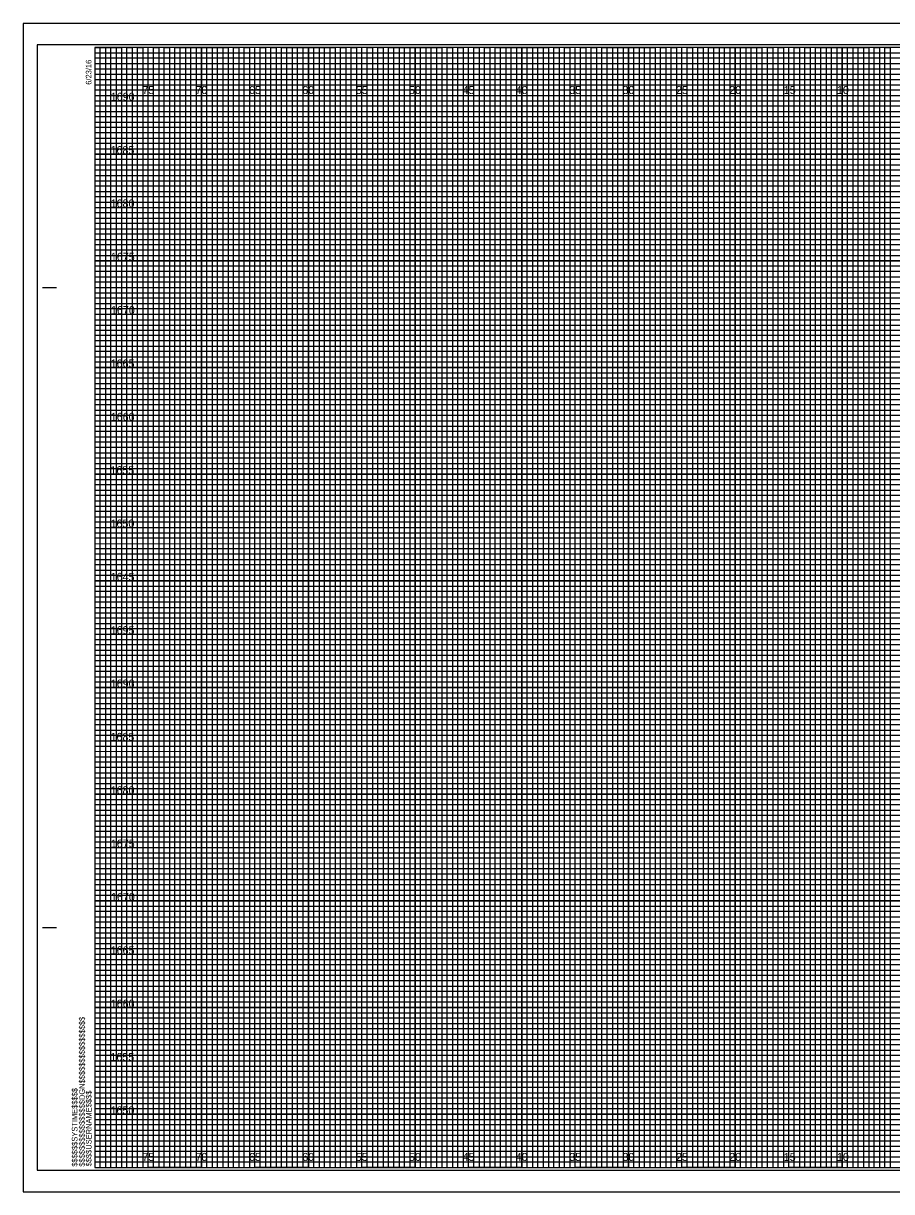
# Model space of a CAD drawing. Extents: x 224 to 392, y 1 to 440.
# Drawn here: x 223.6 to 304.9, y 111 to 220.5 of the extents above; entities that cross this region are included whole.
import ezdxf

# ---------------------------------------------------------------- set-up
doc = ezdxf.new("R2010")
doc.units = 0
for name, color, linetype in [('Prop Grid Mask', 7, 'Continuous'), ('Prop XS Elevation Labels', 7, 'Continuous'), ('Sheet Cross Section CELL', 7, 'Continuous'), ('Sheet Cross Section Grid Major CELL', 7, 'Continuous'), ('Sheet Cross Section Grid Middle CELL', 7, 'Continuous'), ('Sheet Cross Section Grid Minor 1 CELL', 7, 'Continuous'), ('Sheet Cross Section Grid Minor 2 CELL', 7, 'Continuous'), ('Sheet Cutting Line CELL', 7, 'Continuous'), ('Sheet DOT Grid CELL', 7, 'Continuous'), ('Sheet Plot Border Inside CELL', 7, 'Continuous'), ('Sheet Plot Border Outside CELL', 7, 'Continuous')]:
    doc.layers.add(name, color=color, linetype=linetype)

msp = doc.modelspace()

# ---------------------------------------------------------------- linework, layer by layer
at = {"layer": 'Sheet Cross Section CELL'}
for p, q in [((225.36, 195.71), (226.61, 195.71)), ((225.41, 195.71), (226.66, 195.71)), ((225.36, 135.71), (226.61, 135.71)), ((225.41, 135.71), (226.66, 135.71)), ((230.26, 113.21), (230.26, 113.21)), ((230.26, 113.21), (230.26, 113.21)), ((230.26, 113.21), (230.26, 113.21)), ((230.26, 113.21), (230.26, 113.21)), ((230.26, 113.21), (230.26, 113.21)), ((230.26, 113.21), (230.26, 113.21)), ((230.26, 113.21), (230.26, 113.21))]:
    msp.add_line(p, q, dxfattribs=at)
msp.add_lwpolyline([(390.26, 218.21), (230.26, 218.21), (230.26, 113.21), (390.26, 113.21)], close=True, dxfattribs=at)
at = {"layer": 'Sheet Cross Section Grid Major CELL'}
for p, q in [((235.26, 218.21), (230.26, 218.21)), ((235.26, 113.21), (235.26, 218.21)), ((245.26, 218.21), (240.26, 218.21)), ((240.26, 218.21), (240.26, 113.21)), ((245.26, 113.21), (245.26, 218.21)), ((255.26, 218.21), (250.26, 218.21)), ((250.26, 218.21), (250.26, 113.21)), ((255.26, 113.21), (255.26, 218.21)), ((265.26, 218.21), (260.26, 218.21)), ((260.26, 218.21), (260.26, 113.21)), ((265.26, 113.21), (265.26, 218.21)), ((275.26, 218.21), (270.26, 218.21)), ((270.26, 218.21), (270.26, 113.21)), ((275.26, 113.21), (275.26, 218.21)), ((285.26, 218.21), (280.26, 218.21)), ((280.26, 218.21), (280.26, 113.21)), ((285.26, 113.21), (285.26, 218.21)), ((295.26, 218.21), (290.26, 218.21)), ((290.26, 218.21), (290.26, 113.21)), ((295.26, 113.21), (295.26, 218.21)), ((305.26, 218.21), (300.26, 218.21)), ((300.26, 218.21), (300.26, 113.21)), ((240.26, 113.21), (235.26, 113.21)), ((250.26, 113.21), (245.26, 113.21)), ((260.26, 113.21), (255.26, 113.21)), ((270.26, 113.21), (265.26, 113.21)), ((280.26, 113.21), (275.26, 113.21)), ((290.26, 113.21), (285.26, 113.21)), ((300.26, 113.21), (295.26, 113.21))]:
    msp.add_line(p, q, dxfattribs=at)
for points in [[(230.26, 213.21), (390.26, 213.21), (390.26, 208.21), (230.26, 208.21)], [(230.26, 203.21), (390.26, 203.21), (390.26, 198.21), (230.26, 198.21)], [(230.26, 193.21), (390.26, 193.21), (390.26, 188.21), (230.26, 188.21)], [(230.26, 183.21), (390.26, 183.21), (390.26, 178.21), (230.26, 178.21)], [(230.26, 173.21), (390.26, 173.21), (390.26, 168.21), (230.26, 168.21)], [(230.26, 163.21), (390.26, 163.21), (390.26, 158.21), (230.26, 158.21)], [(230.26, 153.21), (390.26, 153.21), (390.26, 148.21), (230.26, 148.21)], [(230.26, 143.21), (390.26, 143.21), (390.26, 138.21), (230.26, 138.21)], [(230.26, 133.21), (390.26, 133.21), (390.26, 128.21), (230.26, 128.21)], [(230.26, 123.21), (390.26, 123.21), (390.26, 118.21), (230.26, 118.21)]]:
    msp.add_lwpolyline(points, dxfattribs=at)
at = {"layer": 'Sheet Cross Section Grid Middle CELL'}
for points in [[(230.26, 218.21), (232.76, 218.21), (232.76, 113.21), (237.76, 113.21), (237.76, 218.21), (242.76, 218.21), (242.76, 113.21), (247.76, 113.21), (247.76, 218.21), (252.76, 218.21), (252.76, 113.21), (257.76, 113.21), (257.76, 218.21), (262.76, 218.21), (262.76, 113.21), (267.76, 113.21), (267.76, 218.21), (272.76, 218.21), (272.76, 113.21), (277.76, 113.21), (277.76, 218.21), (282.76, 218.21), (282.76, 113.21), (287.76, 113.21), (287.76, 218.21), (292.76, 218.21), (292.76, 113.21), (297.76, 113.21), (297.76, 218.21), (302.76, 218.21), (302.76, 113.21), (307.76, 113.21)], [(230.26, 215.71), (367.76, 215.71)], [(230.26, 205.71), (390.26, 205.71), (390.26, 210.71), (230.26, 210.71)], [(230.26, 195.71), (390.26, 195.71), (390.26, 200.71), (230.26, 200.71)], [(230.26, 185.71), (390.26, 185.71), (390.26, 190.71), (230.26, 190.71)], [(230.26, 175.71), (390.26, 175.71), (390.26, 180.71), (230.26, 180.71)], [(230.26, 165.71), (390.26, 165.71), (390.26, 170.71), (230.26, 170.71)], [(230.26, 155.71), (390.26, 155.71), (390.26, 160.71), (230.26, 160.71)], [(230.26, 145.71), (390.26, 145.71), (390.26, 150.71), (230.26, 150.71)], [(230.26, 135.71), (390.26, 135.71), (390.26, 140.71), (230.26, 140.71)], [(230.26, 125.71), (390.26, 125.71), (390.26, 130.71), (230.26, 130.71)], [(230.26, 115.71), (390.26, 115.71), (390.26, 120.71), (230.26, 120.71)]]:
    msp.add_lwpolyline(points, dxfattribs=at)
at = {"layer": 'Sheet Cross Section Grid Minor 1 CELL'}
for p, q in [((230.26, 217.71), (360.26, 217.71)), ((360.26, 217.2), (230.26, 217.2)), ((230.26, 217.2), (230.26, 216.71)), ((230.26, 216.71), (360.26, 216.71)), ((360.26, 216.16), (230.26, 216.16)), ((230.26, 216.16), (230.26, 215.21)), ((230.26, 215.21), (390.26, 215.21))]:
    msp.add_line(p, q, dxfattribs=at)
for points in [[(230.26, 214.71), (365.26, 214.71), (390.26, 214.71), (390.26, 214.21), (230.26, 214.21)], [(230.26, 213.71), (390.26, 213.71), (390.26, 212.71), (230.26, 212.71)], [(230.26, 212.21), (390.26, 212.21), (390.26, 211.71), (230.26, 211.7)], [(230.26, 211.21), (390.26, 211.21), (390.26, 210.21), (230.26, 210.21)], [(230.26, 209.71), (390.26, 209.71), (390.26, 209.21), (230.26, 209.21)], [(230.26, 208.71), (390.26, 208.71), (390.26, 207.71), (230.26, 207.71)], [(230.26, 207.21), (390.26, 207.21), (390.26, 206.71), (230.26, 206.71)], [(230.26, 206.21), (390.26, 206.21), (390.26, 205.21), (230.26, 205.21)], [(230.26, 204.71), (390.26, 204.71), (390.26, 204.21), (230.26, 204.21)], [(230.26, 203.71), (390.26, 203.71), (390.26, 202.71), (230.26, 202.71)], [(230.26, 202.21), (390.26, 202.21), (390.26, 201.71), (230.26, 201.71)], [(230.26, 201.21), (390.26, 201.21), (390.26, 200.19), (390.26, 199.71), (390.26, 199.21), (230.26, 199.21)], [(230.26, 200.21), (390.26, 200.21), (390.26, 199.71), (230.26, 199.71)], [(230.26, 198.71), (390.26, 198.71), (390.26, 197.71), (230.26, 197.73)], [(230.26, 197.73), (390.26, 197.71), (390.26, 197.21), (230.26, 197.21)], [(230.26, 196.71), (390.26, 196.71), (390.26, 196.21), (230.26, 196.21)], [(230.26, 195.21), (390.26, 195.21), (390.26, 194.71), (230.26, 194.71)], [(230.26, 194.21), (390.26, 194.21), (390.26, 193.71), (230.26, 193.71)], [(230.23, 192.66), (390.26, 192.66), (390.26, 192.15), (230.23, 192.15)], [(230.26, 191.71), (390.26, 191.71), (390.26, 191.21), (230.26, 191.21)], [(230.26, 190.21), (390.26, 190.21), (390.26, 189.71), (230.26, 189.71)], [(230.26, 189.21), (390.26, 189.21), (390.26, 188.71), (230.26, 188.71)], [(230.26, 187.71), (390.26, 187.71), (390.26, 187.21), (230.26, 187.21)], [(230.26, 186.71), (390.26, 186.71), (390.26, 186.21), (230.26, 186.21)], [(230.26, 185.21), (390.26, 185.21), (390.26, 184.71), (230.26, 184.71)], [(230.26, 184.21), (390.26, 184.21), (390.26, 183.71), (230.26, 183.71)], [(230.26, 182.71), (390.26, 182.71), (390.26, 182.2), (230.26, 182.21)], [(230.26, 181.71), (390.26, 181.71), (390.26, 181.21), (230.26, 181.21)], [(230.26, 180.21), (390.26, 180.21), (390.26, 179.71), (230.26, 179.71)], [(230.26, 179.21), (390.26, 179.21), (390.26, 178.71), (230.26, 178.71)], [(230.26, 177.71), (390.26, 177.71), (390.26, 177.21), (230.26, 177.21)], [(230.26, 176.71), (390.26, 176.71), (390.26, 176.21), (230.26, 176.21)], [(230.26, 175.21), (390.26, 175.21), (390.26, 174.71), (230.26, 174.71)], [(230.26, 174.21), (390.26, 174.21), (390.26, 173.71), (230.26, 173.71)], [(230.26, 172.71), (390.26, 172.71), (390.26, 172.21), (230.26, 172.21)], [(230.26, 171.71), (390.3, 171.67), (390.26, 171.21), (230.26, 171.21)], [(230.26, 170.21), (390.26, 170.21), (390.26, 169.71), (230.26, 169.71)], [(230.26, 169.21), (390.26, 169.21), (390.26, 168.71), (230.26, 168.71)], [(230.26, 167.71), (390.26, 167.71), (390.26, 167.21), (230.26, 167.21)], [(230.26, 166.71), (390.26, 166.71), (390.26, 166.21), (230.26, 166.21)], [(230.26, 165.21), (390.26, 165.21), (390.26, 164.71), (230.26, 164.71)], [(230.26, 164.21), (390.26, 164.21), (390.26, 163.71), (230.26, 163.71)], [(230.26, 162.71), (390.26, 162.71), (390.26, 162.21), (230.26, 162.21)], [(230.26, 161.71), (390.26, 161.71), (390.26, 161.21), (230.26, 161.21)], [(230.26, 160.21), (390.26, 160.21), (390.26, 159.71), (230.26, 159.71)], [(230.26, 159.21), (390.26, 159.21), (390.26, 158.71), (230.26, 158.71)], [(230.26, 157.71), (390.26, 157.71), (390.26, 157.21), (230.26, 157.21)], [(230.26, 156.71), (390.26, 156.71), (390.26, 156.21), (230.26, 156.21)], [(230.26, 155.21), (390.26, 155.21), (390.26, 154.71), (230.26, 154.71)], [(230.26, 154.21), (390.26, 154.21), (390.26, 153.71), (230.26, 153.71)], [(230.26, 152.71), (390.26, 152.71), (390.26, 152.2), (230.26, 152.21)], [(230.26, 151.71), (390.26, 151.71), (390.26, 151.21), (230.26, 151.21)], [(230.26, 150.21), (390.26, 150.21), (390.26, 149.71), (230.26, 149.71)], [(230.26, 149.21), (390.26, 149.21), (390.26, 148.71), (230.26, 148.71)], [(230.26, 147.71), (390.26, 147.71), (390.26, 147.21), (230.26, 147.21)], [(230.26, 146.71), (390.26, 146.71), (390.26, 146.21), (230.26, 146.21)], [(230.26, 145.21), (390.26, 145.21), (390.26, 144.71), (230.26, 144.71)], [(230.26, 144.21), (390.26, 144.21), (390.26, 143.71), (230.26, 143.71)], [(230.26, 142.71), (390.26, 142.71), (390.26, 142.21), (230.26, 142.21)], [(230.26, 141.71), (390.3, 141.67), (390.26, 141.21), (230.26, 141.21)], [(230.26, 140.21), (390.26, 140.21), (390.26, 139.71), (230.26, 139.71)], [(230.26, 139.21), (390.26, 139.21), (390.26, 138.71), (230.26, 138.71)], [(230.26, 137.71), (390.26, 137.71), (390.26, 137.21), (230.26, 137.21)], [(230.26, 136.71), (390.26, 136.71), (390.26, 136.21), (230.26, 136.21)], [(230.26, 135.21), (390.26, 135.21), (390.26, 134.71), (230.26, 134.71)], [(230.26, 134.21), (390.26, 134.21), (390.26, 133.71), (230.26, 133.71)], [(230.26, 132.71), (390.26, 132.71), (390.26, 132.21), (230.26, 132.21)], [(230.26, 131.71), (390.26, 131.71), (390.26, 131.21), (230.26, 131.21)], [(230.26, 130.21), (390.26, 130.21), (390.26, 129.71), (230.26, 129.71)], [(230.26, 129.21), (390.26, 129.21), (390.26, 128.71), (230.26, 128.71)], [(230.26, 127.71), (390.26, 127.71), (390.26, 127.21), (230.26, 127.21)], [(230.26, 126.71), (390.26, 126.71), (390.26, 126.21), (230.26, 126.21)], [(230.26, 125.21), (390.26, 125.21), (390.26, 124.71), (230.26, 124.71)], [(230.26, 124.21), (390.26, 124.21), (390.26, 123.71), (230.26, 123.71)], [(230.26, 122.71), (390.26, 122.71), (390.26, 122.21), (230.26, 122.21)], [(230.26, 121.71), (390.26, 121.71), (390.26, 121.21), (230.26, 121.21)], [(230.26, 120.21), (390.26, 120.21), (390.26, 119.71), (230.26, 119.71)], [(230.26, 119.21), (390.26, 119.21), (390.26, 118.71), (230.26, 118.71)], [(230.26, 117.71), (390.26, 117.71), (390.26, 117.21), (230.26, 117.21)], [(230.26, 116.71), (390.26, 116.71), (390.26, 116.21), (230.26, 116.21)], [(230.26, 115.21), (390.26, 115.21), (390.26, 114.71), (230.26, 114.71)], [(230.26, 114.21), (390.26, 114.21), (390.26, 113.71), (230.26, 113.71)]]:
    msp.add_lwpolyline(points, dxfattribs=at)
at = {"layer": 'Sheet Cross Section Grid Minor 2 CELL'}
for points in [[(230.26, 113.21), (230.76, 113.21), (230.76, 218.21), (231.26, 218.21), (231.26, 113.21)], [(231.26, 113.21), (231.76, 113.21), (231.76, 218.21), (232.26, 218.21), (232.26, 113.21)], [(232.76, 113.21), (233.26, 113.21), (233.26, 218.21), (233.76, 218.21), (233.76, 113.21)], [(233.76, 113.21), (234.26, 113.21), (234.26, 218.21), (234.76, 218.21), (234.76, 113.21)], [(235.26, 113.21), (235.76, 113.21), (235.76, 218.21), (236.26, 218.21), (236.26, 113.21)], [(236.26, 113.21), (236.76, 113.21), (236.76, 218.21), (237.26, 218.21), (237.26, 113.21)], [(237.76, 113.21), (238.26, 113.21), (238.26, 218.21), (238.76, 218.21), (238.76, 113.21)], [(238.76, 113.21), (239.26, 113.21), (239.26, 218.21), (239.76, 218.21), (239.76, 113.21)], [(240.26, 113.21), (240.76, 113.21), (240.76, 218.21), (241.26, 218.21), (241.26, 113.21)], [(241.26, 113.21), (241.76, 113.21), (241.76, 218.21), (242.26, 218.21), (242.26, 113.21)], [(242.76, 113.21), (243.26, 113.21), (243.26, 218.21), (243.76, 218.21), (243.76, 113.21)], [(243.76, 113.21), (244.26, 113.21), (244.26, 218.21), (244.76, 218.21), (244.76, 113.21)], [(245.26, 113.21), (245.76, 113.21), (245.76, 218.21), (246.26, 218.21), (246.26, 113.21)], [(246.26, 113.21), (246.76, 113.21), (246.76, 218.21), (247.26, 218.21), (247.26, 113.21)], [(247.76, 113.21), (248.26, 113.21), (248.26, 218.21), (248.76, 218.21), (248.76, 113.21)], [(248.76, 113.21), (249.26, 113.21), (249.26, 218.21), (249.76, 218.21), (249.76, 113.21)], [(250.26, 113.21), (250.76, 113.21), (250.76, 218.21), (251.26, 218.21), (251.26, 113.21)], [(251.26, 113.21), (251.76, 113.21), (251.76, 218.21), (252.26, 218.21), (252.26, 113.21)], [(252.76, 113.21), (253.26, 113.21), (253.26, 218.21), (253.76, 218.21), (253.76, 113.21)], [(253.76, 113.21), (254.26, 113.21), (254.26, 218.21), (254.76, 218.21), (254.76, 113.21)], [(255.26, 113.21), (255.76, 113.21), (255.76, 218.21), (256.26, 218.21), (256.26, 113.21)], [(256.26, 113.21), (256.76, 113.21), (256.76, 218.21), (257.26, 218.21), (257.26, 113.21)], [(257.76, 113.21), (258.26, 113.21), (258.26, 218.21), (258.76, 218.21), (258.76, 113.21)], [(258.76, 113.21), (259.26, 113.21), (259.26, 218.21), (259.76, 218.21), (259.76, 113.21)], [(260.26, 113.21), (260.76, 113.21), (260.76, 218.21), (261.26, 218.21), (261.26, 113.21)], [(261.26, 113.21), (261.76, 113.21), (261.76, 218.21), (262.26, 218.21), (262.26, 113.21)], [(262.76, 113.21), (263.26, 113.21), (263.26, 218.21), (263.76, 218.21), (263.76, 113.21)], [(263.76, 113.21), (264.26, 113.21), (264.26, 218.21), (264.76, 218.21), (264.76, 113.21)], [(265.26, 113.21), (265.76, 113.21), (265.76, 218.21), (266.26, 218.21), (266.26, 113.21)], [(266.26, 113.21), (266.76, 113.21), (266.76, 218.21), (267.26, 218.21), (267.26, 113.21)], [(267.76, 113.21), (268.26, 113.21), (268.26, 218.21), (268.76, 218.21), (268.76, 113.21)], [(268.76, 113.21), (269.26, 113.21), (269.26, 218.21), (269.76, 218.21), (269.76, 113.21)], [(270.26, 113.21), (270.76, 113.21), (270.76, 218.21), (271.26, 218.21), (271.26, 113.21)], [(271.26, 113.21), (271.76, 113.21), (271.76, 218.21), (272.26, 218.21), (272.26, 113.21)], [(272.76, 113.21), (273.26, 113.21), (273.26, 218.21), (273.76, 218.21), (273.76, 113.21)], [(273.76, 113.21), (274.26, 113.21), (274.26, 218.21), (274.76, 218.21), (274.76, 113.21)], [(275.26, 113.21), (275.76, 113.21), (275.76, 218.21), (276.26, 218.21), (276.26, 113.21)], [(276.26, 113.21), (276.76, 113.21), (276.76, 218.21), (277.26, 218.21), (277.26, 113.21)], [(277.76, 113.21), (278.26, 113.21), (278.26, 218.21), (278.76, 218.21), (278.76, 113.21)], [(278.76, 113.21), (279.26, 113.21), (279.26, 218.21), (279.76, 218.21), (279.76, 113.21)], [(280.26, 113.21), (280.76, 113.21), (280.76, 218.21), (281.26, 218.21), (281.26, 113.21)], [(281.26, 113.21), (281.76, 113.21), (281.76, 218.21), (282.26, 218.21), (282.26, 113.21)], [(282.76, 113.21), (283.26, 113.21), (283.26, 218.21), (283.76, 218.21), (283.76, 113.21)], [(283.76, 113.21), (284.26, 113.21), (284.26, 218.21), (284.76, 218.21), (284.76, 113.21)], [(285.26, 113.21), (285.76, 113.21), (285.76, 218.21), (286.26, 218.21), (286.26, 113.21)], [(286.26, 113.21), (286.76, 113.21), (286.76, 218.21), (287.26, 218.21), (287.26, 113.21)], [(287.76, 113.21), (288.26, 113.21), (288.26, 218.21), (288.76, 218.21), (288.76, 113.21)], [(288.76, 113.21), (289.26, 113.21), (289.26, 218.21), (289.76, 218.21), (289.76, 113.21)], [(290.26, 113.21), (290.76, 113.21), (290.76, 218.21), (291.26, 218.21), (291.26, 113.21)], [(291.26, 113.21), (291.76, 113.21), (291.76, 218.21), (292.26, 218.21), (292.26, 113.21)], [(292.76, 113.21), (293.26, 113.21), (293.26, 218.21), (293.76, 218.21), (293.76, 113.21)], [(293.76, 113.21), (294.26, 113.21), (294.26, 218.21), (294.76, 218.21), (294.76, 113.21)], [(295.26, 113.21), (295.76, 113.21), (295.76, 218.21), (296.26, 218.21), (296.26, 113.21)], [(296.26, 113.21), (296.76, 113.21), (296.76, 218.21), (297.26, 218.21), (297.26, 113.21)], [(297.76, 113.21), (298.26, 113.21), (298.26, 218.21), (298.76, 218.21), (298.76, 113.21)], [(298.76, 113.21), (299.26, 113.21), (299.26, 218.21), (299.76, 218.21), (299.76, 113.21)], [(300.26, 113.21), (300.76, 113.21), (300.76, 218.21), (301.26, 218.21), (301.26, 113.21)], [(301.26, 113.21), (301.76, 113.21), (301.76, 218.21), (302.26, 218.21), (302.26, 113.21)], [(302.76, 113.21), (303.26, 113.21), (303.26, 218.21), (303.76, 218.21), (303.76, 113.21)], [(303.76, 113.21), (304.26, 113.21), (304.26, 218.21), (304.76, 218.21), (304.76, 113.21)]]:
    msp.add_lwpolyline(points, dxfattribs=at)
at = {"layer": 'Sheet Cutting Line CELL'}
for p, q in [((391.91, 220.46), (223.56, 220.46)), ((223.56, 220.46), (223.56, 110.96)), ((223.56, 110.96), (391.91, 110.96))]:
    msp.add_line(p, q, dxfattribs=at)
at = {"layer": 'Sheet DOT Grid CELL'}
for p, q in [((235.26, 113.21), (235.26, 218.21)), ((240.26, 113.21), (240.26, 218.21)), ((245.26, 113.21), (245.26, 218.21)), ((250.26, 113.21), (250.26, 218.21)), ((255.26, 113.21), (255.26, 218.21)), ((260.26, 113.21), (260.26, 218.21)), ((265.26, 113.21), (265.26, 218.21)), ((270.26, 113.21), (270.26, 218.21)), ((275.26, 113.21), (275.26, 218.21)), ((280.26, 113.21), (280.26, 218.21)), ((285.26, 113.21), (285.26, 218.21)), ((290.26, 113.21), (290.26, 218.21)), ((295.26, 113.21), (295.26, 218.21)), ((300.26, 113.21), (300.26, 218.21)), ((230.26, 213.21), (390.26, 213.21)), ((230.26, 208.21), (390.26, 208.21)), ((230.26, 203.21), (390.26, 203.21)), ((230.26, 198.21), (390.26, 198.21)), ((230.26, 193.21), (390.26, 193.21)), ((230.26, 188.21), (390.26, 188.21)), ((230.26, 183.21), (390.26, 183.21)), ((230.26, 178.21), (390.26, 178.21)), ((230.26, 173.21), (390.26, 173.21)), ((230.26, 168.21), (390.26, 168.21)), ((230.26, 163.21), (390.26, 163.21)), ((230.26, 158.21), (390.26, 158.21)), ((230.26, 153.21), (390.26, 153.21)), ((230.26, 148.21), (390.26, 148.21)), ((230.26, 143.21), (390.26, 143.21)), ((230.26, 138.21), (390.26, 138.21)), ((230.26, 133.21), (390.26, 133.21)), ((230.26, 128.21), (390.26, 128.21)), ((230.26, 123.21), (390.26, 123.21)), ((230.26, 118.21), (390.26, 118.21))]:
    msp.add_line(p, q, dxfattribs=at)
at = {"layer": 'Sheet Plot Border Inside CELL'}
msp.add_lwpolyline([(224.86, 112.96), (391.46, 112.96), (391.46, 218.46), (224.86, 218.46)], close=True, dxfattribs=at)
at = {"layer": 'Sheet Plot Border Outside CELL'}
msp.add_lwpolyline([(223.56, 110.96), (391.91, 110.96), (391.91, 220.46), (223.56, 220.46)], close=True, dxfattribs=at)

# ---------------------------------------------------------------- texts
at = {"layer": 'Prop Grid Mask'}
for s, p in [('75', (234.71, 213.84)), ('70', (239.69, 213.84)), ('65', (244.71, 213.84)), ('60', (249.69, 213.84)), ('55', (254.71, 213.84)), ('50', (259.69, 213.84)), ('45', (264.71, 213.84)), ('40', (269.69, 213.84)), ('35', (274.71, 213.84)), ('30', (279.69, 213.84)), ('25', (284.71, 213.84)), ('20', (289.69, 213.84)), ('15', (294.8, 213.84)), ('10', (299.78, 213.84)), ('75', (234.71, 113.84)), ('70', (239.69, 113.84)), ('65', (244.71, 113.84)), ('60', (249.69, 113.84)), ('55', (254.71, 113.84)), ('50', (259.69, 113.84)), ('45', (264.71, 113.84)), ('40', (269.69, 113.84)), ('35', (274.71, 113.84)), ('30', (279.69, 113.84)), ('25', (284.71, 113.84)), ('20', (289.69, 113.84)), ('15', (294.8, 113.84)), ('10', (299.78, 113.84))]:
    msp.add_text(s, height=0.75, dxfattribs=at).set_placement(p)
at = {"layer": 'Prop XS Elevation Labels'}
for s, p in [('1690', (231.75, 213.21)), ('1685', (231.73, 208.21)), ('1680', (231.74, 203.21)), ('1675', (231.76, 198.21)), ('1670', (231.77, 193.21)), ('1665', (231.74, 188.21)), ('1660', (231.75, 183.21)), ('1655', (231.72, 178.21)), ('1650', (231.73, 173.21)), ('1645', (231.74, 168.21)), ('1695', (231.74, 163.21)), ('1690', (231.75, 158.21)), ('1685', (231.73, 153.21)), ('1680', (231.74, 148.21)), ('1675', (231.76, 143.21)), ('1670', (231.77, 138.21)), ('1665', (231.74, 133.21)), ('1660', (231.75, 128.21)), ('1655', (231.72, 123.21)), ('1650', (231.73, 118.21))]:
    msp.add_text(s, height=0.75, dxfattribs=at).set_placement(p)
at = {"layer": 'Sheet Cross Section CELL'}
for s, p in [('6/23/16', (229.94, 214.71)), ('$$$$$$$$$$$$$$$$DGN$$$$$$$$$$$$$$$$', (229.32, 113.3)), ('$$$$$$SYSTIME$$$$$', (228.63, 113.3)), ('$$$$USERNAME$$$$', (229.95, 113.33))]:
    msp.add_text(s, height=0.525, rotation=90, dxfattribs=at).set_placement(p)

doc.saveas('drawing.dxf')
